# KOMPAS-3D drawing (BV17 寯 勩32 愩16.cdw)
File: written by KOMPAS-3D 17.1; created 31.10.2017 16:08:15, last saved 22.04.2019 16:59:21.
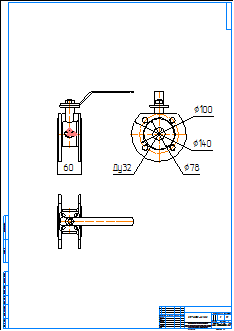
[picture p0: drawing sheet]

Sheet 1: A1, portrait

Title block, sheet 1: name: BV17 МФ Ду32 Ру16; material: Внимание! Данный продукт является объектом авторского права ООО «Торговый Дом АДЛ». / Запрещается изменение, копирование, распространение / (в том числе путем копирования на другие сайты и ресурсы в Интернете) / или любое иное использование информации и объектов без предварительного / согласия правообладателя (ООО «Торговый Дом АДЛ»).; mass: 1; sheets: 1; organisation: ООО "Торговый дом АДЛ"; sheet format: A1; stored path: \\adlc.lan\data\АДЛ_ПКД\3D-модели\ADL production\Краны шаровые серии BV\BV17 МФ Нержавеющие Ру16\KOMPAS 2D\BV17 МФ Ду32 Ру16.cdw

Views: Вид 1, Проекционный вид 2, Проекционный вид 3
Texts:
  kka
  adl
Dimensions and other numbers on the sheet: 60; 32; 140; 100; 78; 1:1; 1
